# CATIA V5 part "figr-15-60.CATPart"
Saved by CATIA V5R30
Part number: Part1
Bounding box of the stored display mesh (mm): x -35.944 to 35.944, y -33.497 to 33.497, z 0 to 50.428
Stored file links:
  D:\PROJECTS\CATIA V56R 2020\Resources\Parts File\c15_catia_v5_6r2020_prt\figr-15-60.CATPart
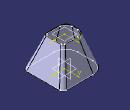
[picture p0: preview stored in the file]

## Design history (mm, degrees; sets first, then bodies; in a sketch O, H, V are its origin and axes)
SheetMetalParameters1: Thickness 1, BendRadius 2, KFactor 0.400515 {= log(min(100,max(20*SheetMetalParameters1.BendRadius,SheetMetalParameters1.Thickness)/SheetMetalParameters1.Thickness))/log(100)/2}, ReliefRadialLength 1, ReliefAxialLength 2, MinimumBendRadius 0
Body1 (main body)
  Sketch1 on xy-plane, origin (0, 0, 0), H (1, 0, 0), V (0, 1, 0)
    line L1 (-15, -32.5532) -> (30, -32.5532)
    line L2 (35, -27.5532) -> (35, 27.5532)
    line L3 (30, 32.5532) -> (-15, 32.5532)
    line L4 (-35, 12.5532) -> (-35, -12.5532)
    arc A1 centre (-15, -12.5532) radius 20 from (-35, -12.5532) to (-15, -32.5532) ccw
    arc A2 centre (-15, 12.5532) radius 20 from (-35, 12.5532) to (-15, 32.5532) cw
    arc A3 centre (30, -27.5532) radius 5 from (30, -32.5532) to (35, -27.5532) ccw
    arc A4 centre (30, 27.5532) radius 5 from (35, 27.5532) to (30, 32.5532) ccw
    radius A1 = 20
    radius A2 = 20
    radius A3 = 5
    radius A4 = 5
    distance L2 L4 = 70
    horizontal: L1 H, L3 H
    vertical: L2 V, L4 V
    tangency: A1 L4, A1 L1, A2 L4, A2 L3, A3 L1, A3 L2, A4 L2, A4 L3
    symmetry: L3 L1 H, L4 L2 V
  Plane1: type Offset, RefPlane xy-plane, Offset 50
  Sketch2 "Sketch.2" on Plane1, origin (0, 0, 50), H (1, 0, 0), V (0, 1, 0)
    line L1 (-7.5, 15) -> (14.5, 15)
    line L2 (17.5, 12) -> (17.5, -12)
    line L3 (14.5, -15) -> (-7.5, -15)
    line L4 (-17.5, -5) -> (-17.5, 5)
    arc A1 centre (-7.5, -5) radius 10 from (-7.5, -15) to (-17.5, -5) cw
    arc A2 centre (-7.5, 5) radius 10 from (-17.5, 5) to (-7.5, 15) cw
    arc A3 centre (14.5, 12) radius 3 from (14.5, 15) to (17.5, 12) cw
    arc A4 centre (14.5, -12) radius 3 from (17.5, -12) to (14.5, -15) cw
    radius A1 = 10
    radius A2 = 10
    radius A3 = 3
    radius A4 = 3
    distance L4 L2 = 35
    distance L1 L3 = 30
    horizontal: L1 H, L3 H
    vertical: L2 V, L4 V
    tangency: A1 L3, A1 L4, A2 L4, A2 L1, A3 L1, A3 L2, A4 L2, A4 L3
    symmetry: L4 L2 V, L1 L3 H
  Hopper1: KFacteur 0.400515 {= SheetMetalParameters1.KFactor}, HopperFixedSideType 0, HopperType 0, Hopper_InvariantPoint vertex [element of Sketch1 | element of Sketch1], Hopper_NeutralFiber 0, Hopper_ReferenceEdge edge [face of Hopper1 | face of Hopper1], Hopper_Surface {loft Sections (Sketch1; Sketch2), SectionCouplingPoints ({coupling CouplingPoints (vertex [element of Sketch1 | element of Sketch1]; vertex [element of Sketch2 | element of Sketch2])}; {coupling CouplingPoints (vertex [element of Sketch1 | element of Sketch1]; vertex [element of Sketch2 | element of Sketch2])}; {coupling CouplingPoints (vertex [element of Sketch1 | element of Sketch1]; vertex [element of Sketch2 | element of Sketch2])}; {coupling CouplingPoints (vertex [element of Sketch1 | element of Sketch1]; vertex [element of Sketch2 | element of Sketch2])}; {coupling CouplingPoints (vertex [element of Sketch1 | element of Sketch1]; vertex [element of Sketch2 | element of Sketch2])}; {coupling CouplingPoints (vertex [element of Sketch1 | element of Sketch1]; vertex [element of Sketch2 | element of Sketch2])}; {coupling CouplingPoints (vertex [element of Sketch1 | element of Sketch1]; vertex [element of Sketch2 | element of Sketch2])}; {coupling CouplingPoints (vertex [element of Sketch1 | element of Sketch1]; vertex [element of Sketch2 | element of Sketch2])})}, Hopper_TearWires edge [face of Hopper1 | face of Hopper1], Hopper_Thickness 1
